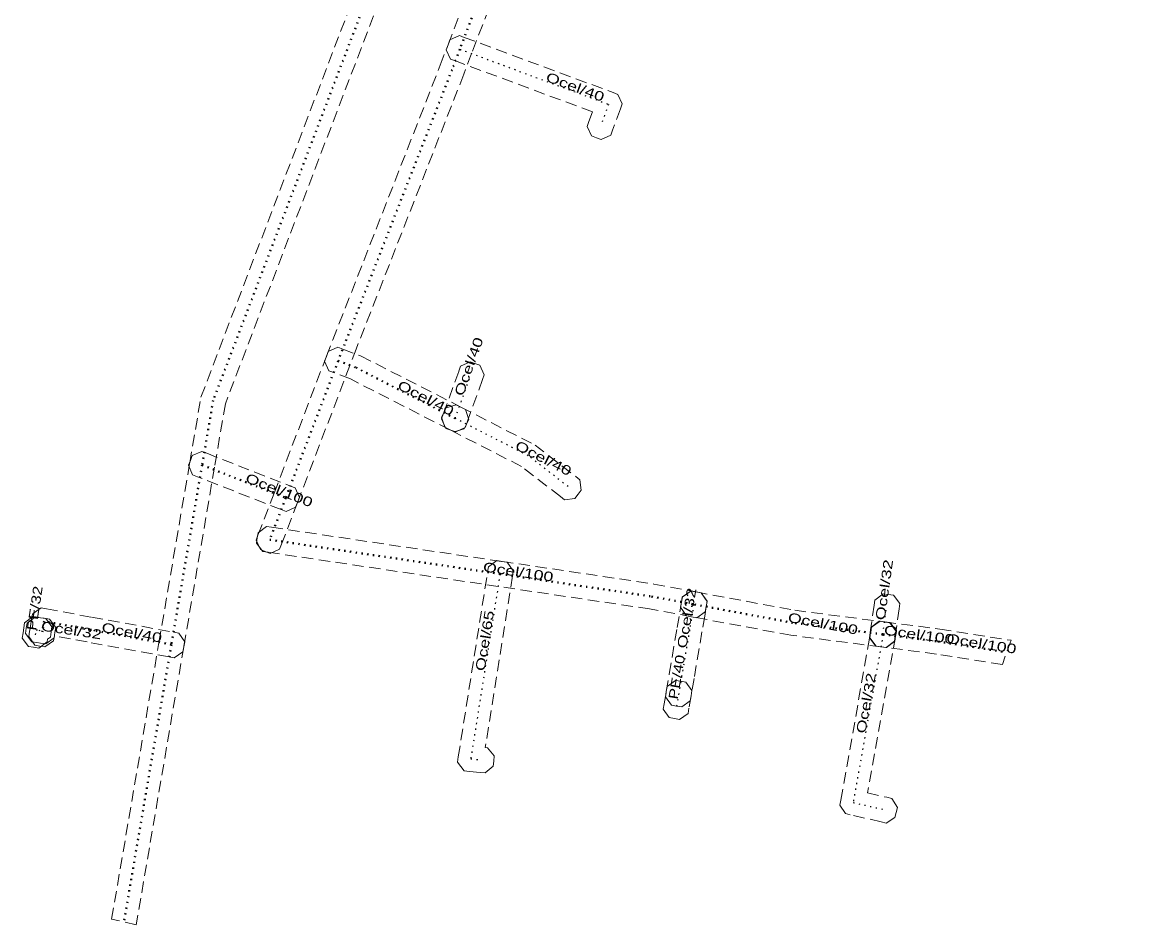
# Model space of a CAD drawing. Extents: x -644301 to -644150, y -1042432 to -1042139.
# Drawn here: x -644301 to -644212.7, y -1042431.7 to -1042360.2 of the extents above; entities that cross this region are included whole.
import ezdxf

# ---------------------------------------------------------------- set-up
doc = ezdxf.new("R2010")
doc.units = 0
doc.header["$LTSCALE"] = 0.3
doc.linetypes.add('DOTTED', pattern=[1.5, 0.3, -1.2])
doc.linetypes.add('MEDIUM_DASHED', pattern=[4.5, 3, -1.5])
doc.layers.add('1', color=7, linetype='MEDIUM_DASHED', lineweight=13)
doc.layers.add('18', color=7, linetype='DOTTED', lineweight=25)
doc.layers.add('20', color=7, linetype='Continuous')

msp = doc.modelspace()

# ---------------------------------------------------------------- linework, layer by layer
at = {"layer": '1'}
for points in [[(-644237.888, -1042269.645), (-644248.531, -1042295.264), (-644252.728, -1042306.532), (-644264.437, -1042336.864), (-644272.664, -1042358.382), (-644284.912, -1042390.417), (-644285.773, -1042395.45), (-644288.212, -1042409.691), (-644291.99, -1042431.748), (-644293.942, -1042431.295), (-644290.184, -1042409.353), (-644287.745, -1042395.112), (-644286.85, -1042389.887), (-644274.532, -1042357.668), (-644266.303, -1042336.146), (-644254.598, -1042305.822), (-644250.393, -1042294.532), (-644239.756, -1042268.927)], [(-644260.168, -1042348.984), (-644265.362, -1042362.646), (-644265.983, -1042364.281), (-644274.525, -1042386.079), (-644275.02, -1042387.373), (-644279.183, -1042398.241), (-644280.456, -1042401.564), (-644280.604, -1042401.951), (-644281.361, -1042402.288), (-644281.748, -1042402.14), (-644282.135, -1042401.992), (-644282.472, -1042401.235), (-644282.324, -1042400.848), (-644281.051, -1042397.525), (-644276.888, -1042386.657), (-644276.389, -1042385.357), (-644267.849, -1042363.561), (-644267.232, -1042361.936), (-644262.038, -1042348.274)]]:
    msp.add_lwpolyline(points, dxfattribs=at)
for points in [[(-644266.338, -1042361.209), (-644265.949, -1042361.353), (-644254.135, -1042365.733), (-644253.747, -1042365.877), (-644253.402, -1042366.629), (-644253.545, -1042367.017), (-644254.175, -1042368.723), (-644254.318, -1042369.112), (-644255.07, -1042369.458), (-644255.459, -1042369.315), (-644255.848, -1042369.172), (-644256.194, -1042368.42), (-644256.051, -1042368.031), (-644255.767, -1042367.261), (-644266.645, -1042363.229), (-644267.033, -1042363.085), (-644267.379, -1042362.332), (-644267.235, -1042361.943), (-644267.091, -1042361.555)], [(-644266.755, -1042392.658), (-644267.124, -1042392.469), (-644274.986, -1042388.452), (-644276.309, -1042387.95), (-644276.696, -1042387.803), (-644277.036, -1042387.047), (-644276.889, -1042386.66), (-644276.742, -1042386.273), (-644275.986, -1042385.933), (-644275.599, -1042386.08), (-644274.174, -1042386.62), (-644266.214, -1042390.689), (-644265.845, -1042390.877), (-644265.59, -1042391.665), (-644265.779, -1042392.034), (-644265.967, -1042392.403)], [(-644267.75, -1042391.629), (-644267.61, -1042391.24), (-644266.378, -1042387.826), (-644266.237, -1042387.436), (-644265.487, -1042387.084), (-644265.098, -1042387.224), (-644264.708, -1042387.365), (-644264.356, -1042388.115), (-644264.496, -1042388.504), (-644265.728, -1042391.918), (-644265.869, -1042392.308), (-644266.619, -1042392.66), (-644267.008, -1042392.52), (-644267.398, -1042392.379)], [(-644257.985, -1042398.034), (-644258.313, -1042397.781), (-644261.405, -1042395.392), (-644267.124, -1042392.469), (-644267.493, -1042392.281), (-644267.748, -1042391.493), (-644267.559, -1042391.124), (-644267.371, -1042390.755), (-644266.583, -1042390.5), (-644266.214, -1042390.689), (-644260.329, -1042393.696), (-644257.091, -1042396.199), (-644256.763, -1042396.452), (-644256.658, -1042397.273), (-644256.911, -1042397.601), (-644257.164, -1042397.929)], [(-644286.78, -1042394.199), (-644286.394, -1042394.35), (-644279.752, -1042396.952), (-644279.366, -1042397.103), (-644279.035, -1042397.862), (-644279.186, -1042398.248), (-644279.337, -1042398.634), (-644280.096, -1042398.965), (-644280.482, -1042398.814), (-644287.124, -1042396.212), (-644287.51, -1042396.061), (-644287.841, -1042395.302), (-644287.69, -1042394.916), (-644287.539, -1042394.53)], [(-644281.653, -1042400.156), (-644281.243, -1042400.217), (-644262.958, -1042402.931), (-644250.907, -1042404.72), (-644247.535, -1042405.348), (-644247.128, -1042405.424), (-644246.659, -1042406.107), (-644246.735, -1042406.514), (-644246.811, -1042406.921), (-644247.494, -1042407.39), (-644247.901, -1042407.314), (-644251.237, -1042406.692), (-644263.252, -1042404.909), (-644281.537, -1042402.195), (-644281.947, -1042402.134), (-644282.44, -1042401.469), (-644282.379, -1042401.059), (-644282.318, -1042400.649)], [(-644262.117, -1042404.077), (-644264.278, -1042417.694), (-644264.099, -1042417.711), (-644263.57, -1042418.348), (-644263.608, -1042418.76), (-644263.647, -1042419.173), (-644264.284, -1042419.702), (-644264.696, -1042419.664), (-644265.525, -1042419.587), (-644265.957, -1042419.547), (-644266.223, -1042419.204), (-644266.489, -1042418.862), (-644266.421, -1042418.434), (-644264.093, -1042403.763), (-644264.028, -1042403.354), (-644263.357, -1042402.867), (-644262.948, -1042402.932), (-644262.539, -1042402.997), (-644262.052, -1042403.668)], [(-644246.663, -1042406.09), (-644246.732, -1042406.498), (-644246.861, -1042407.259), (-644247.075, -1042408.517), (-644247.703, -1042412.203), (-644247.938, -1042413.586), (-644248.008, -1042413.994), (-644248.684, -1042414.473), (-644249.092, -1042414.404), (-644249.5, -1042414.334), (-644249.979, -1042413.658), (-644249.91, -1042413.25), (-644249.675, -1042411.867), (-644249.047, -1042408.181), (-644248.833, -1042406.923), (-644248.704, -1042406.164), (-644248.635, -1042405.756), (-644247.959, -1042405.276), (-644247.551, -1042405.345), (-644247.143, -1042405.414)], [(-644232.442, -1042409.76), (-644232.853, -1042409.707), (-644240.021, -1042408.782), (-644247.901, -1042407.314), (-644248.308, -1042407.238), (-644248.777, -1042406.555), (-644248.701, -1042406.148), (-644248.625, -1042405.741), (-644247.942, -1042405.272), (-644247.535, -1042405.348), (-644239.709, -1042406.806), (-644232.597, -1042407.723), (-644232.186, -1042407.776), (-644231.68, -1042408.432), (-644231.733, -1042408.843), (-644231.786, -1042409.254)], [(-644233.773, -1042408.986), (-644233.715, -1042408.576), (-644233.409, -1042406.403), (-644233.351, -1042405.993), (-644232.69, -1042405.494), (-644232.28, -1042405.552), (-644231.87, -1042405.61), (-644231.371, -1042406.271), (-644231.429, -1042406.681), (-644231.735, -1042408.854), (-644231.793, -1042409.264), (-644232.454, -1042409.763), (-644232.864, -1042409.705), (-644233.274, -1042409.647)], [(-644295.891, -1042409.317), (-644298.489, -1042408.843), (-644298.555, -1042409.229), (-644299.232, -1042409.708), (-644299.64, -1042409.638), (-644300.048, -1042409.568), (-644300.527, -1042408.891), (-644300.457, -1042408.483), (-644300.418, -1042408.257), (-644300.291, -1042407.51), (-644300.221, -1042407.099), (-644299.879, -1042406.859), (-644299.537, -1042406.619), (-644299.126, -1042406.694), (-644295.533, -1042407.349), (-644289.018, -1042408.538), (-644288.611, -1042408.613), (-644288.14, -1042409.294), (-644288.214, -1042409.702), (-644288.289, -1042410.109), (-644288.97, -1042410.58), (-644289.378, -1042410.506)], [(-644298.8, -1042408.936), (-644299.03, -1042409.107), (-644299.061, -1042409.306), (-644299.728, -1042409.797), (-644300.138, -1042409.735), (-644300.547, -1042409.672), (-644301.038, -1042409.005), (-644300.976, -1042408.595), (-644300.916, -1042408.201), (-644300.854, -1042407.793), (-644300.19, -1042407.303), (-644299.782, -1042407.363), (-644299.584, -1042407.392), (-644299.174, -1042407.452), (-644298.68, -1042408.116), (-644298.74, -1042408.526)], [(-644299.992, -1042407.331), (-644299.582, -1042407.392), (-644299.285, -1042407.436), (-644298.875, -1042407.496), (-644298.382, -1042408.162), (-644298.443, -1042408.572), (-644298.503, -1042408.982), (-644299.169, -1042409.475), (-644299.579, -1042409.414), (-644299.876, -1042409.37), (-644300.286, -1042409.31), (-644300.779, -1042408.644), (-644300.718, -1042408.234), (-644300.658, -1042407.824)], [(-644231.639, -1042408.487), (-644231.712, -1042408.895), (-644233.924, -1042421.286), (-644232.404, -1042421.64), (-644232.001, -1042421.734), (-644231.563, -1042422.438), (-644231.657, -1042422.841), (-644231.751, -1042423.244), (-644232.455, -1042423.682), (-644232.858, -1042423.588), (-644235.302, -1042423.018), (-644235.69, -1042422.927), (-644236.129, -1042422.261), (-644236.059, -1042421.868), (-644233.68, -1042408.543), (-644233.608, -1042408.135), (-644232.928, -1042407.662), (-644232.52, -1042407.735), (-644232.112, -1042407.807)], [(-644232.998, -1042407.668), (-644232.588, -1042407.724), (-644232.559, -1042407.728), (-644232.149, -1042407.785), (-644231.649, -1042408.446), (-644231.705, -1042408.856), (-644231.762, -1042409.266), (-644232.423, -1042409.766), (-644232.833, -1042409.71), (-644232.862, -1042409.706), (-644233.272, -1042409.649), (-644233.772, -1042408.988), (-644233.716, -1042408.578), (-644233.659, -1042408.168)], [(-644222.534, -1042409.186), (-644223.224, -1042411.102), (-644228.467, -1042410.272), (-644232.824, -1042409.711), (-644233.235, -1042409.658), (-644233.741, -1042409.002), (-644233.688, -1042408.591), (-644233.635, -1042408.18), (-644232.979, -1042407.674), (-644232.568, -1042407.727), (-644228.183, -1042408.292)], [(-644247.868, -1042413.178), (-644247.938, -1042413.586), (-644248.106, -1042414.572), (-644248.176, -1042414.98), (-644248.852, -1042415.46), (-644249.26, -1042415.39), (-644249.668, -1042415.32), (-644250.148, -1042414.644), (-644250.078, -1042414.236), (-644249.91, -1042413.25), (-644249.84, -1042412.842), (-644249.164, -1042412.362), (-644248.756, -1042412.432), (-644248.348, -1042412.502)]]:
    msp.add_lwpolyline(points, close=True, dxfattribs=at)
at = {"layer": '18'}
for p, q in [((-644266.669, -1042391.579), (-644265.437, -1042388.165)), ((-644232.725, -1042408.715), (-644232.419, -1042406.542))]:
    msp.add_line(p, q, dxfattribs=at)
at = {"layer": '18', "lineweight": 40}
for p, q in [((-644286.759, -1042395.281), (-644280.117, -1042397.883)), ((-644232.725, -1042408.715), (-644232.696, -1042408.719))]:
    msp.add_line(p, q, dxfattribs=at)
for points in [[(-644214.767, -1042197.36), (-644213.51, -1042198.468), (-644221.219, -1042219.86), (-644227.935, -1042238.495), (-644228.551, -1042240.204), (-644235.868, -1042260.921), (-644238.822, -1042269.286), (-644249.462, -1042294.898), (-644253.663, -1042306.177), (-644265.37, -1042336.505), (-644273.598, -1042358.025), (-644285.881, -1042390.152), (-644286.759, -1042395.281), (-644289.198, -1042409.522), (-644292.966, -1042431.522)], [(-644212.717, -1042220.969), (-644219.305, -1042239.03), (-644219.946, -1042240.7), (-644222.743, -1042247.984), (-644229.688, -1042266.072), (-644232.379, -1042273.081), (-644232.992, -1042274.676), (-644241.698, -1042297.579), (-644242.274, -1042299.095), (-644244.78, -1042305.687), (-644253.829, -1042329.493), (-644255.179, -1042333.045), (-644255.896, -1042334.931), (-644261.103, -1042348.629), (-644266.297, -1042362.291), (-644266.916, -1042363.921), (-644275.457, -1042385.718), (-644275.954, -1042387.015), (-644280.117, -1042397.883), (-644281.39, -1042401.206)], [(-644266.669, -1042391.579), (-644274.58, -1042387.536), (-644275.954, -1042387.015)], [(-644281.39, -1042401.206), (-644263.105, -1042403.92), (-644251.072, -1042405.706), (-644247.718, -1042406.331)], [(-644232.725, -1042408.715), (-644239.865, -1042407.794), (-644247.718, -1042406.331)], [(-644289.198, -1042409.522), (-644295.712, -1042408.333), (-644299.305, -1042407.678), (-644299.432, -1042408.425), (-644299.471, -1042408.652)], [(-644232.696, -1042408.719), (-644228.325, -1042409.282), (-644222.879, -1042410.144)]]:
    msp.add_lwpolyline(points, dxfattribs=at)
at = {"layer": '18'}
for points in [[(-644266.297, -1042362.291), (-644254.483, -1042366.671), (-644255.113, -1042368.377)], [(-644257.702, -1042396.99), (-644260.867, -1042394.544), (-644266.669, -1042391.579)], [(-644263.105, -1042403.92), (-644265.433, -1042418.591), (-644264.604, -1042418.668)], [(-644247.718, -1042406.331), (-644247.847, -1042407.091), (-644248.061, -1042408.349), (-644248.689, -1042412.035), (-644248.924, -1042413.418), (-644249.092, -1042414.404)], [(-644299.987, -1042408.746), (-644299.927, -1042408.352), (-644299.729, -1042408.381), (-644299.432, -1042408.425)], [(-644232.696, -1042408.719), (-644235.075, -1042422.044), (-644232.631, -1042422.614)]]:
    msp.add_lwpolyline(points, dxfattribs=at)

# ---------------------------------------------------------------- texts
at = {"layer": '20'}
for s, rotation, width, p in [('Ocel/40', 339.658, 1.4, (-644259.537, -1042364.797)), ('Ocel/40', 70.157, 1.4, (-644266.053, -1042389.872)), ('Ocel/40', 332.93, 1.4, (-644271.323, -1042389.2)), ('Ocel/40', 332.932, 1.4, (-644261.987, -1042393.971)), ('Ocel/100', 338.607, 1.4, (-644283.391, -1042396.6)), ('Ocel/100', 351.557, 1.4, (-644264.494, -1042403.714)), ('Ocel/32', 81.984, 1.4, (-644232.572, -1042407.628)), ('PE/32', 81.341, 1.3, (-644299.942, -1042408.45)), ('Ocel/32', 80.331, 1.4, (-644248.321, -1042409.874)), ('Ocel/32', 351.573, 1.4, (-644299.58, -1042408.403)), ('Ocel/65', 80.983, 1.4, (-644264.334, -1042411.666)), ('Ocel/100', 349.447, 1.4, (-644240.302, -1042407.712)), ('Ocel/40', 349.656, 1.4, (-644294.786, -1042408.502)), ('Ocel/100', 352.147, 1.4, (-644232.661, -1042408.724)), ('Ocel/100', 351.004, 1.4, (-644227.729, -1042409.376)), ('PE/40', 80.33, 1.3, (-644249.008, -1042413.911)), ('Ocel/32', 79.877, 1.4, (-644234.106, -1042416.617))]:
    msp.add_text(s, height=0.75, rotation=rotation, dxfattribs=dict(at, width=width)).set_placement(p)

doc.saveas('drawing.dxf')
